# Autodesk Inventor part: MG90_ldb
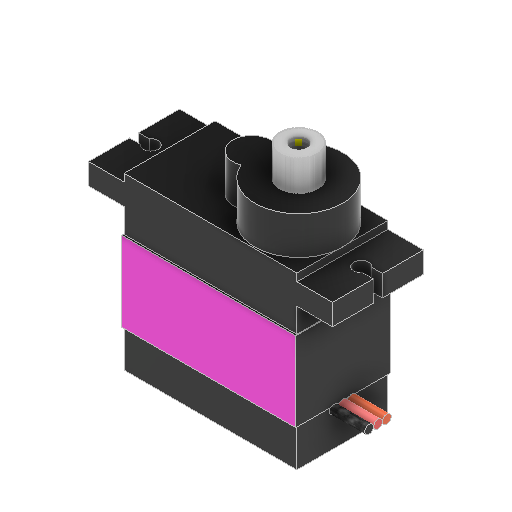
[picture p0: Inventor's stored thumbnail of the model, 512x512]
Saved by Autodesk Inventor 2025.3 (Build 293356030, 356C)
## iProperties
Created: 2019-07
Part Number: MG90_ldb
Material: Steel
Document SubType Name: Modeling
Designer: admin
Density: 7.85 g/cm^3
Appearance: Default
Sending System: Autodesk Translation Framework v8.2.0.1029
Preprocessor: ST-DEVELOPER v18
Title: D:/Development/3dprint/VictorsTests/StandardParts/MG90_Rebuild.step
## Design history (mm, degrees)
feature "WireHardCoded"
feature "Filettatura1" dims "d0" = 4, "d1" = 0
node "Piano di lavoro1"
sketch "Schizzo2"
  geometry: L1 (5.8, 0)-(-5.309, 0) reference; L2 (-0.05, 4)-(0.05, 4); L3 (0.05, 4)-(0.05, 0); L4 (0.05, 0)-(-0.05, 0); L5 (-0.05, 0)-(-0.05, 4); L6 (0, 0)-(0, 2.124); L7 (2.5, 4)-(-2.5, 4) reference; 2 further points
  constraints: 10 end point, 3 parallel, 2 midpoint, 1 horizontal, 1 perpendicular, 1 point on line, 1 other
  dimensions: "d2" = 0.1 distance of L3.end L4.end
extrude "Estrusione1" cut sketch "Schizzo2" distance "d3" = 0.1; taper "d4" = 0 deg
sketch "Schizzo3"
  geometry: 1 further point
node "Solido1"
pattern_circular "Serie circolare1" dims angle "d6" = 360 deg
